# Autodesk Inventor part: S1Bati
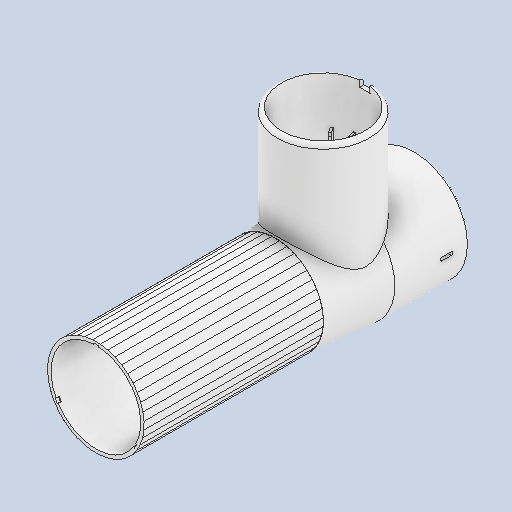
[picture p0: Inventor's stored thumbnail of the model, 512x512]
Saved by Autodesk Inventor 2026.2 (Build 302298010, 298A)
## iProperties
Created: 1601-01
Part Number: S1Bati
Material: ABS
Document SubType Name: Modeling
Designer: mel
Density: 1.02 g/cm^3
Appearance: white-pw-mt11050
Author: mel
Sending System: SOLIDWORKS 2023
Part Number: Bati
Last Saved Date: 2025-04-02
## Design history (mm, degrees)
feature "Boss.-Extru.16"
node "Plan1"
node "Plan2"
node "Plan3"
node "Plan4"
node "Plan5"
node "Plan6"
node "Solide1"
